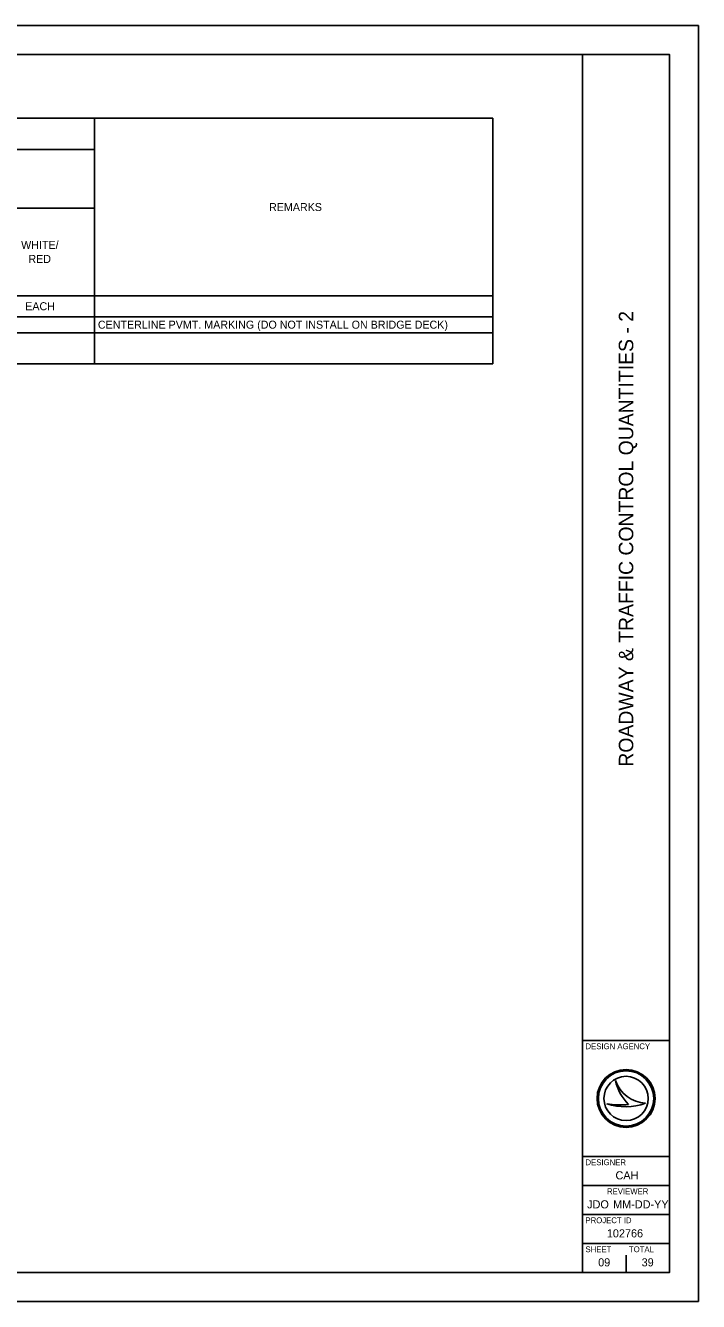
# Model space of a CAD drawing. Extents: x 0 to 34, y 0 to 22.
# Drawn here: x 22.39 to 34, y 0 to 22 of the extents above; entities that cross this region are included whole.
import ezdxf

# ---------------------------------------------------------------- set-up
doc = ezdxf.new("R2010")
doc.units = 0
for name, color, linetype in [('Default', 7, 'Continuous'), ('SH_Border', 7, 'Continuous'), ('SH_Cut_Line', 7, 'Continuous'), ('SH_Data', 7, 'Continuous'), ('SH_Text', 7, 'Continuous')]:
    doc.layers.add(name, color=color, linetype=linetype)

msp = doc.modelspace()

# ---------------------------------------------------------------- linework, layer by layer
at = {"layer": 'Default'}
msp.add_line((30.454, 20.4), (30.454, 16.164), dxfattribs=at)
at = {"layer": 'SH_Border'}
for p, q in [((32, 0.5), (32, 21.5)), ((32, 4.5), (33.5, 4.5)), ((32, 2.5), (33.5, 2.5)), ((32, 2), (33.5, 2)), ((32, 1.5), (33.5, 1.5)), ((32, 1), (33.5, 1))]:
    msp.add_line(p, q, dxfattribs=at)
msp.add_lwpolyline([(1.5, 21.5), (33.5, 21.5), (33.5, 0.5), (1.5, 0.5)], close=True, dxfattribs=at)
at = {"layer": 'SH_Cut_Line'}
msp.add_lwpolyline([(0, 0), (34, 0), (34, 22), (0, 22)], close=True, dxfattribs=at)
at = {"layer": 'SH_Data'}
for p, q in [((32.567, 3.81), (32.567, 3.81)), ((32.417, 3.41), (32.417, 3.41)), ((32.75, 3.5), (32.75, 3.5)), ((33.087, 3.419), (33.087, 3.419)), ((32.375, 0.675), (32.375, 0.675)), ((32.75, 0.5), (32.75, 0.8))]:
    msp.add_line(p, q, dxfattribs=at)
for radius in [0.5, 0.477, 0.477, 0.382]:
    msp.add_circle((32.75, 3.5), radius, dxfattribs=at)
for centre, radius, start, end in [((33.116, 3.998), 0.58, 198.9257, 198.9319), ((33.347, 3.97), 0.796, 191.6379, 191.6421), ((33.116, 3.998), 0.58, 198.9319, 267.1657), ((33.347, 3.97), 0.796, 191.6421, 226.0947), ((32.739, 4.37), 1.013, 251.4576, 290.0832), ((32.648, 4.654), 1.266, 259.4964, 259.4995), ((32.739, 4.37), 1.013, 251.4527, 251.4576), ((32.648, 4.654), 1.266, 259.4995, 276.6672)]:
    msp.add_arc(centre, radius, start, end, dxfattribs=at)
at = {"layer": 'SH_Text'}
for p, q in [((9.178, 20.4), (23.578, 20.4)), ((23.578, 20.4), (29.362, 20.4)), ((23.578, 20.4), (23.578, 18.852)), ((29.362, 20.4), (30.454, 20.4)), ((30.454, 20.4), (30.454, 18.852)), ((13.978, 19.86), (23.578, 19.86)), ((13.978, 18.852), (23.578, 18.852)), ((23.578, 18.852), (23.578, 16.164)), ((30.454, 18.852), (30.454, 16.164)), ((12.058, 17.34), (23.578, 17.34)), ((23.578, 17.34), (29.362, 17.34)), ((29.362, 17.34), (30.454, 17.34)), ((9.178, 16.98), (23.578, 16.98)), ((23.578, 16.98), (29.362, 16.98)), ((29.362, 16.98), (30.454, 16.98)), ((9.178, 16.704), (23.578, 16.704)), ((23.578, 16.704), (29.362, 16.704)), ((29.362, 16.704), (30.454, 16.704)), ((9.178, 16.164), (23.578, 16.164)), ((23.578, 16.164), (29.362, 16.164)), ((29.362, 16.164), (30.454, 16.164))]:
    msp.add_line(p, q, dxfattribs=at)

# ---------------------------------------------------------------- texts
at = {"layer": 'SH_Data'}
msp.add_text('ROADWAY & TRAFFIC CONTROL QUANTITIES - 2', height=0.25, rotation=90, dxfattribs=at).set_placement((32.875, 9.221))
for s, height, p in [('DESIGN AGENCY', 0.1, (32.05, 4.35)), ('DESIGNER', 0.1, (32.05, 2.35)), ('CAH', 0.14, (32.568, 2.105)), ('REVIEWER', 0.1, (32.422, 1.85)), ('JDO', 0.14, (32.079, 1.605)), ('MM-DD-YY', 0.14, (32.527, 1.605)), ('PROJECT ID', 0.1, (32.05, 1.35)), ('102766', 0.14, (32.419, 1.105)), ('SHEET', 0.1, (32.05, 0.85)), ('TOTAL', 0.1, (32.8, 0.85)), ('09', 0.14, (32.269, 0.605)), ('39', 0.14, (33.019, 0.605))]:
    msp.add_text(s, height=height, dxfattribs=at).set_placement(p)
at = {"layer": 'SH_Text'}
for s, p in [('REMARKS', (26.591, 18.801)), ('WHITE/', (22.314, 18.148)), ('RED', (22.439, 17.906)), ('EACH', (22.384, 17.091)), ('CENTERLINE PVMT. MARKING (DO NOT INSTALL ON BRIDGE DECK)', (23.638, 16.773))]:
    msp.add_text(s, height=0.138, dxfattribs=at).set_placement(p)

doc.saveas('drawing.dxf')
